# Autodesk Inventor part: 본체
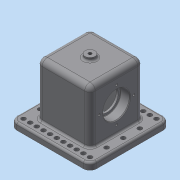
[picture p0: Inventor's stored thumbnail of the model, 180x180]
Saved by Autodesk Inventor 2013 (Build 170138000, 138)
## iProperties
Created: 2018-11
Part Number: 본체
Material: 일반
Document SubType Name: Modeling
Designer: dgall
Density: 1 g/cm^3
Mass: 376.663 g
Surface Area: 777.082 cm^2
Volume: 376.663 cm^3
Author: dgall
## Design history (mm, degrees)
sketch "스케치1"
  geometry: L1 (-40, 40)-(40, 40); L2 (40, 40)-(40, -40); L3 (40, -40)-(-40, -40); L4 (-40, -40)-(-40, 40); 3 further points
  constraints: 8 end point, 2 midpoint, 2 parallel, 1 horizontal, 1 horizontal alignment, 1 perpendicular, 1 vertical alignment
  dimensions: "d0" = 80 distance of L2.end L3.end; "d1" = 80 distance of L1.end L2.end
extrude "돌출1" new body sketch "스케치1" stored distance "d2" = 90; taper "d3" = 0 deg
sketch "스케치3"
  geometry: L1 (23, 35)-(-23, 35); L2 (-23, 35)-(-23, -45); L3 (-23, -45)-(23, -45); L4 (23, -45)-(23, 35); L5 (40, -45)-(-40, -45) reference; 3 further points
  constraints: 8 end point, 3 midpoint, 2 parallel, 1 horizontal, 1 perpendicular, 1 vertical alignment
  dimensions: "d6" = 46 distance of L2.end L3.end; "d8" = 80 distance of L1.end L2.end
sketch "스케치4"
  geometry: L1 (90, 80)-(90, 0) reference; C1 r 20 at (42, 40); 1 further point
  constraints: 1 centre point, 1 horizontal alignment
  dimensions: "d11" = 40 diameter of C1; "d12" = 48 distance from line of L1 C1.centre
extrude "돌출3" cut sketch "스케치4" distance "d13" = 14; taper "d14" = 0 deg
hole "구멍1" diameter "d17" = 33; stored, may be unused: countersink angle "d21" = 90 deg, drill point angle "d23" = 118 deg; dims "d15" = 10, "d16" = 10, "d18" = 6, "d19" = 4, "d20" = 2, "d22" = 8
sketch "스케치5" dims "d24" = 52
  geometry: C1 r 20 at (42, 40) reference; C2 r 2 at (16, 40); 2 further points
  constraints: 2 horizontal alignment, 1 centre point, 1 coincident, 2 other
  dimensions: "d25" = 4 diameter of C2
hole "구멍2" sketch "스케치5" at (16, 40) diameter "d26" = 3.242; stored, may be unused: countersink angle "d30" = 90 deg, drill point angle "d32" = 118 deg; dims "d27" = 8, "d28" = 4, "d29" = 2, "d31" = 10
node "작업 평면1"
sketch "스케치6"
  geometry: L1 (-60, 60)-(60, 60); L2 (60, 60)-(60, -60); L3 (60, -60)-(-60, -60); L4 (-60, -60)-(-60, 60); C1 r 3.3 at (-50, -50); C2 r 3.3 at (50, -50); 3 further points
  constraints: 8 end point, 2 centre point, 2 midpoint, 2 parallel, 1 horizontal, 1 horizontal alignment, 1 perpendicular, 1 vertical alignment
  dimensions: "d37" = 120 distance of L2.end L3.end; "d38" = 120 distance of L1.end L2.end; "d39" = 6.6 diameter of C1; "d40" = 10 distance from line of L3 C1.centre; "d41" = 10 distance from line of L4 C1.centre; "d49" = 6.6 diameter of C2; "d50" = 10 distance from line of L3 C2.centre; "d51" = 10 distance from line of L2 C2.centre
extrude "돌출4" join sketch "스케치6" distance "d42" = 10; taper "d43" = 0 deg
extrude "돌출5" cut sketch "스케치6" stored distance "d44" = 10; taper "d45" = 0 deg
extrude "돌출6" cut sketch "스케치6" stored distance "d52" = 10; taper "d53" = 0 deg
extrude "돌출7" cut sketch "스케치3" stored distance "d63" = 60; taper "d64" = 0 deg
sketch "스케치7"
  geometry: C1 r 7.5 at (0, 0); 1 further point
  constraints: 1 centre point, 1 coincident
  dimensions: "d65" = 15 diameter of C1
extrude "돌출8" join sketch "스케치7" distance "d66" = 5; taper "d67" = 0 deg
fillet "모깎기1" dims "d68" = 8
fillet "모깎기2" dims "d69" = 8
hole "구멍3" diameter "d72" = 4.917; stored, may be unused: countersink angle "d76" = 90 deg, drill point angle "d78" = 118 deg; dims "d70" = 10, "d71" = 10, "d73" = 8, "d74" = 4, "d75" = 2, "d77" = 10
fillet "모깎기4" dims "d80" = 3
fillet "모깎기5" dims "d81" = 3
fillet "모깎기6" dims "d82" = 3
fillet "모깎기7" dims "d83" = 3
fillet "모깎기8" dims "d84" = 0.6
chamfer "모따기1" distance "d85" = 1; stored, may be unused: second distance "d86" = 2, angle "d87" = 45 deg
sketch "스케치8"
  geometry: L1 (-28, 82)-(92, 82) reference; 2 further points
  constraints: 1 vertical alignment, 1 other
  dimensions: "d88" = 48 distance from line of L1 point (32, 34)
feature "엠보싱1" sketch "스케치8" dims "d14" = 0, "d89" = 0.5, "d90" = 0
fillet "모깎기9" dims "d91" = 10
fillet "모깎기10" dims "d92" = 3
node "솔리드1"
pattern_circular "원형 패턴1" dims angle "d34" = 360 deg
mirror "대칭1"
pattern_linear "직사각형 패턴2" dims "d56" = 10
pattern_linear "직사각형 패턴3" dims "d59" = 25
pattern_linear "직사각형 패턴4" dims "d62" = 25
mirror "대칭2"
other parameters: "d36" = -45
